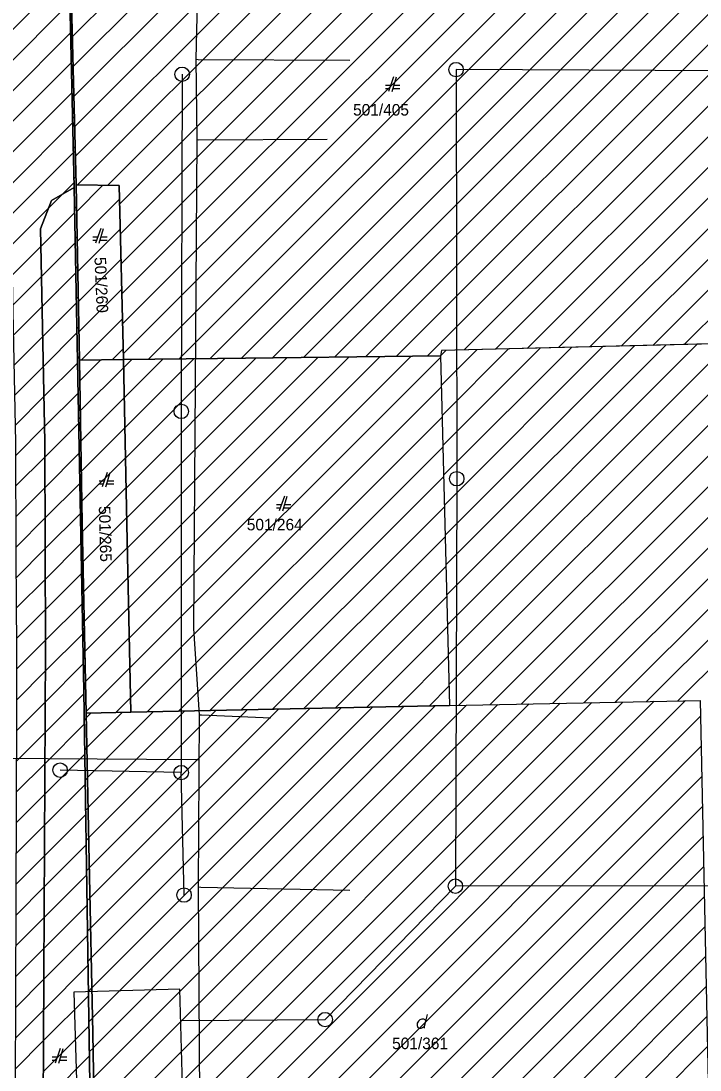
# Model space of a CAD drawing. Extents: x -264309 to -263505, y -1242443 to -1241763.
# Drawn here: x -263948.8 to -263854.8, y -1242246.2 to -1242101 of the extents above; entities that cross this region are included whole.
import ezdxf

# ---------------------------------------------------------------- set-up
doc = ezdxf.new("R2010")
doc.units = 0
for name, color, linetype in [('KFA_DAZDOVA_KANALIZACIA_retencna_nadrz', 7, 'Continuous'), ('KFA_DAZDOVA_KANALIZACIA_vetva_G', 7, 'Continuous'), ('KFA_DAZDOVA_KANALIZACIA_vetva_I', 7, 'Continuous'), ('KFA_SO_50-1-II_VODOVODNE_PRIPOJKY', 7, 'Continuous'), ('KFA_SO_50-2_POZIARNY_VODOVOD_TRASA', 7, 'Continuous'), ('KN_2019_08_16_KLADPAR', 7, 'Continuous'), ('SRAFY_PARCELY', 7, 'Continuous')]:
    doc.layers.add(name, color=color, linetype=linetype)

msp = doc.modelspace()

# ---------------------------------------------------------------- linework, layer by layer
at = {"layer": 'KFA_DAZDOVA_KANALIZACIA_retencna_nadrz'}
msp.add_lwpolyline([(-263941.49, -1242235.46), (-263940.97, -1242253.75), (-263926.32, -1242253.31), (-263926.85, -1242235.04)], close=True, dxfattribs=at)
at = {"layer": 'KFA_DAZDOVA_KANALIZACIA_vetva_G'}
for points in [[(-263926.52, -1242108.42), (-263926.64, -1242155.08), (-263926.65, -1242205.07)], [(-263926.26, -1242222.02), (-263926.65, -1242205.07), (-263943.42, -1242204.73)]]:
    msp.add_lwpolyline(points, dxfattribs=at)
for centre in [(-263926.52, -1242108.42), (-263926.64, -1242155.08), (-263943.42, -1242204.73), (-263926.65, -1242205.07), (-263926.26, -1242222.02)]:
    msp.add_circle(centre, 1, dxfattribs=at)
at = {"layer": 'KFA_DAZDOVA_KANALIZACIA_vetva_I'}
msp.add_line((-263926.72, -1242239.4), (-263906.73, -1242239.26), dxfattribs=at)
for points in [[(-263814.91, -1242107.86), (-263815.2, -1242164.44), (-263815.19, -1242220.79), (-263852.15, -1242220.74), (-263888.7, -1242220.79), (-263906.73, -1242239.26)], [(-263814.91, -1242107.86), (-263851.89, -1242107.95), (-263888.61, -1242107.77), (-263888.52, -1242164.4), (-263888.7, -1242220.79)]]:
    msp.add_lwpolyline(points, dxfattribs=at)
for centre in [(-263888.61, -1242107.77), (-263888.52, -1242164.4), (-263888.7, -1242220.79), (-263906.73, -1242239.26)]:
    msp.add_circle(centre, 1, dxfattribs=at)
at = {"layer": 'KFA_SO_50-1-II_VODOVODNE_PRIPOJKY'}
for points in [[(-263924.64, -1242106.32), (-263924.32, -1242106.37), (-263903.32, -1242106.48)], [(-263924.48, -1242117.43), (-263924.21, -1242117.48), (-263906.47, -1242117.4)], [(-263924.15, -1242197.09), (-263923.86, -1242197.09), (-263914.23, -1242197.47)], [(-263924.19, -1242203.3), (-263924.63, -1242203.3), (-263958.87, -1242203.05)], [(-263924.3, -1242220.9), (-263923.93, -1242220.91), (-263903.3, -1242221.32)]]:
    msp.add_lwpolyline(points, dxfattribs=at)
at = {"layer": 'KFA_SO_50-2_POZIARNY_VODOVOD_TRASA'}
msp.add_lwpolyline([(-263924.93, -1242185.13), (-263924.15, -1242197.09), (-263924.3, -1242220.9), (-263924.1, -1242250.12), (-263913.99, -1242249.8), (-263886.91, -1242249.88), (-263867.71, -1242249.83), (-263837.26, -1242249.84), (-263828.16, -1242249.9), (-263787.99, -1242250.03), (-263788.2, -1242220.84), (-263788.2, -1242200.51), (-263788.09, -1242179.92), (-263788.06, -1242148.96), (-263787.92, -1242127.95), (-263787.95, -1242110.97), (-263788.13, -1242082.54), (-263828.43, -1242082.72), (-263836.78, -1242082.56), (-263867.31, -1242082.61), (-263886.71, -1242082.47), (-263924.08, -1242082.61), (-263924.64, -1242106.32), (-263924.48, -1242117.43)], close=True, dxfattribs=at)
at = {"layer": 'KN_2019_08_16_KLADPAR'}
for p, q in [((-263897.27, -1242108.78), (-263897.97, -1242110.78)), ((-263897.47, -1242110.78), (-263896.87, -1242108.78)), ((-263897.69, -1242109.98), (-263898.37, -1242109.98)), ((-263896.37, -1242109.98), (-263897.23, -1242109.98)), ((-263898.37, -1242110.38), (-263897.83, -1242110.38)), ((-263897.35, -1242110.38), (-263896.37, -1242110.38)), ((-263937.79, -1242129.77), (-263938.49, -1242131.77)), ((-263937.99, -1242131.77), (-263937.39, -1242129.77)), ((-263938.21, -1242130.97), (-263938.89, -1242130.97)), ((-263938.89, -1242131.37), (-263938.35, -1242131.37)), ((-263937.87, -1242131.37), (-263936.89, -1242131.37)), ((-263936.89, -1242130.97), (-263937.75, -1242130.97)), ((-263936.89, -1242163.52), (-263937.59, -1242165.52)), ((-263937.09, -1242165.52), (-263936.49, -1242163.52)), ((-263937.31, -1242164.72), (-263937.99, -1242164.72)), ((-263937.99, -1242165.12), (-263937.45, -1242165.12)), ((-263936.97, -1242165.12), (-263935.99, -1242165.12)), ((-263935.99, -1242164.72), (-263936.85, -1242164.72)), ((-263912.37, -1242166.83), (-263913.07, -1242168.83)), ((-263912.57, -1242168.83), (-263911.97, -1242166.83)), ((-263912.79, -1242168.03), (-263913.47, -1242168.03)), ((-263911.47, -1242168.03), (-263912.33, -1242168.03)), ((-263913.47, -1242168.43), (-263912.93, -1242168.43)), ((-263912.45, -1242168.43), (-263911.47, -1242168.43)), ((-263892.81, -1242239.46), (-263892.54, -1242238.56)), ((-263943.39, -1242243.27), (-263944.09, -1242245.27)), ((-263943.59, -1242245.27), (-263942.99, -1242243.27)), ((-263943.81, -1242244.47), (-263944.49, -1242244.47)), ((-263944.49, -1242244.87), (-263943.95, -1242244.87)), ((-263943.47, -1242244.87), (-263942.49, -1242244.87)), ((-263942.49, -1242244.47), (-263943.35, -1242244.47))]:
    msp.add_line(p, q, dxfattribs=at)
for points in [[(-263945.92, -1242287.35), (-263949.74, -1242287.63), (-263949.41, -1242196.68), (-263949.38, -1242187.85), (-263949.49, -1242175.05), (-263949.55, -1242159.39), (-263950.14, -1242129.96), (-263950.48, -1242111.43), (-263955.8, -1242087.79), (-263956.24, -1242069.24), (-263949.96, -1242070.83), (-263947.13, -1242072.33), (-263942.68, -1242071.91), (-263941.47, -1242124.08), (-263944.59, -1242125.87), (-263946.11, -1242129.79), (-263945.51, -1242159.3), (-263945.41, -1242187.87)], [(-263942.54, -1242071.9), (-263846.54, -1242085.45), (-263846.27, -1242096.79), (-263846.29, -1242099.09), (-263845.63, -1242123.54), (-263845.17, -1242145.54), (-263890.62, -1242146.65), (-263890.76, -1242147.37), (-263921.62, -1242147.75), (-263934.65, -1242147.91), (-263935.23, -1242123.81), (-263941.18, -1242123.7)], [(-263945.92, -1242287.35), (-263945.41, -1242187.87), (-263945.51, -1242159.3), (-263946.11, -1242129.79), (-263944.59, -1242125.87), (-263941.47, -1242124.08), (-263940.13, -1242193.8), (-263938.35, -1242311.44), (-263946.05, -1242311.56)], [(-263940.74, -1242147.99), (-263941.18, -1242123.7), (-263935.23, -1242123.81), (-263934.65, -1242147.91)], [(-263939.79, -1242196.85), (-263940.34, -1242170.51), (-263940.74, -1242147.99), (-263934.65, -1242147.91), (-263934.15, -1242172.94), (-263933.6, -1242196.72)], [(-263934.65, -1242147.91), (-263921.62, -1242147.75), (-263890.76, -1242147.37), (-263889.52, -1242195.8), (-263933.6, -1242196.72), (-263934.15, -1242172.94)], [(-263939.79, -1242196.85), (-263933.6, -1242196.72), (-263889.52, -1242195.8), (-263854.81, -1242195.07), (-263852.5, -1242305.04), (-263931.11, -1242306.7), (-263937.48, -1242306.83), (-263938.02, -1242292.26), (-263938.87, -1242241.14), (-263939.37, -1242217.33)]]:
    msp.add_lwpolyline(points, close=True, dxfattribs=at)
for points in [[(-263942.54, -1242071.9), (-263941.18, -1242123.7), (-263940.74, -1242147.99), (-263940.34, -1242170.51), (-263939.79, -1242196.85), (-263939.37, -1242217.33), (-263938.87, -1242241.14), (-263938.02, -1242292.26), (-263937.48, -1242306.83), (-263937.4, -1242310.7), (-263938.35, -1242311.44), (-263940.13, -1242193.8), (-263941.47, -1242124.08), (-263942.68, -1242071.91)], [(-263892.99, -1242240.45), (-263892.99, -1242240.18), (-263892.81, -1242239.46), (-263892.9, -1242239.28), (-263893.08, -1242239.19), (-263893.35, -1242239.19), (-263893.62, -1242239.28), (-263893.8, -1242239.46), (-263893.98, -1242239.73), (-263893.98, -1242240.09), (-263893.89, -1242240.36), (-263893.71, -1242240.45), (-263893.44, -1242240.45), (-263893.26, -1242240.36), (-263892.99, -1242240.18)]]:
    msp.add_lwpolyline(points, dxfattribs=at)
at = {"layer": 'SRAFY_PARCELY'}
for p, q in [((-263941.72, -1242103.22), (-263914.37, -1242075.88)), ((-263941.61, -1242107.36), (-263910.65, -1242076.4)), ((-263941.5, -1242111.49), (-263906.93, -1242076.93)), ((-263941.39, -1242115.63), (-263903.22, -1242077.45)), ((-263941.28, -1242119.76), (-263899.5, -1242077.98)), ((-263940.98, -1242123.7), (-263895.78, -1242078.5)), ((-263936.82, -1242123.78), (-263892.06, -1242079.02)), ((-263935.17, -1242126.37), (-263888.34, -1242079.55)), ((-263935.07, -1242130.52), (-263884.63, -1242080.07)), ((-263934.97, -1242134.66), (-263880.91, -1242080.6)), ((-263934.87, -1242138.8), (-263877.19, -1242081.12)), ((-263934.77, -1242142.95), (-263873.47, -1242081.65)), ((-263934.67, -1242147.09), (-263869.75, -1242082.17)), ((-263931.21, -1242147.87), (-263866.04, -1242082.7)), ((-263926.91, -1242147.81), (-263862.32, -1242083.22)), ((-263922.62, -1242147.76), (-263858.6, -1242083.75)), ((-263918.32, -1242147.71), (-263854.88, -1242084.27)), ((-263914.02, -1242147.66), (-263851.17, -1242084.8)), ((-263909.73, -1242147.6), (-263847.45, -1242085.32)), ((-263905.43, -1242147.55), (-263846.47, -1242088.58)), ((-263901.14, -1242147.5), (-263846.37, -1242092.73)), ((-263952.08, -1242104.31), (-263942.16, -1242094.39)), ((-263896.84, -1242147.44), (-263846.27, -1242096.87)), ((-263951.3, -1242107.78), (-263942.06, -1242098.54)), ((-263892.55, -1242147.39), (-263846.24, -1242101.08)), ((-263950.52, -1242111.24), (-263941.97, -1242102.68)), ((-263941.98, -1242102.1), (-263941.75, -1242101.87)), ((-263887.49, -1242146.57), (-263846.12, -1242105.21)), ((-263950.41, -1242115.37), (-263941.87, -1242106.83)), ((-263941.88, -1242106.24), (-263941.64, -1242106)), ((-263941.79, -1242110.39), (-263941.54, -1242110.14)), ((-263883.14, -1242146.47), (-263846.01, -1242109.34)), ((-263950.33, -1242119.54), (-263941.77, -1242110.98)), ((-263941.69, -1242114.54), (-263941.43, -1242114.27)), ((-263878.79, -1242146.36), (-263845.9, -1242113.47)), ((-263950.25, -1242123.7), (-263941.68, -1242115.12)), ((-263941.6, -1242118.68), (-263941.32, -1242118.41)), ((-263874.44, -1242146.25), (-263845.79, -1242117.61)), ((-263950.18, -1242127.87), (-263941.58, -1242119.27)), ((-263870.09, -1242146.15), (-263845.68, -1242121.74)), ((-263941.5, -1242122.83), (-263941.21, -1242122.54)), ((-263943.06, -1242124.99), (-263941.49, -1242123.42)), ((-263941.11, -1242127.4), (-263937.48, -1242123.77)), ((-263945, -1242126.93), (-263943.07, -1242125)), ((-263941.04, -1242131.56), (-263935.18, -1242125.71)), ((-263865.74, -1242146.04), (-263845.58, -1242125.88)), ((-263950.1, -1242132.03), (-263945, -1242126.93)), ((-263946.06, -1242132.23), (-263941.4, -1242127.57)), ((-263941.41, -1242126.99), (-263941.13, -1242126.7)), ((-263940.96, -1242135.73), (-263935.08, -1242129.85)), ((-263861.39, -1242145.94), (-263845.49, -1242130.04)), ((-263945.98, -1242136.39), (-263941.32, -1242131.74)), ((-263941.33, -1242131.15), (-263941.05, -1242130.87)), ((-263950.02, -1242136.19), (-263946.06, -1242132.23)), ((-263940.89, -1242139.9), (-263934.98, -1242134)), ((-263857.04, -1242145.83), (-263845.41, -1242134.19)), ((-263949.93, -1242140.35), (-263945.98, -1242136.39)), ((-263945.89, -1242140.55), (-263941.24, -1242135.9)), ((-263941.25, -1242135.31), (-263940.97, -1242135.03)), ((-263941.17, -1242139.48), (-263940.9, -1242139.2)), ((-263940.81, -1242144.07), (-263934.89, -1242138.14)), ((-263949.85, -1242144.51), (-263945.89, -1242140.55)), ((-263945.81, -1242144.71), (-263941.16, -1242140.06)), ((-263941.09, -1242143.64), (-263940.82, -1242143.37)), ((-263940.49, -1242147.99), (-263934.79, -1242142.28)), ((-263949.76, -1242148.67), (-263945.81, -1242144.71)), ((-263945.72, -1242148.86), (-263941.08, -1242144.22)), ((-263936.19, -1242147.93), (-263934.69, -1242146.42)), ((-263890.65, -1242151.51), (-263885.68, -1242146.53)), ((-263845.17, -1242145.54), (-263890.62, -1242146.65)), ((-263890.55, -1242155.64), (-263881.33, -1242146.42)), ((-263890.44, -1242159.78), (-263876.98, -1242146.32)), ((-263890.34, -1242163.92), (-263872.63, -1242146.21)), ((-263890.23, -1242168.05), (-263868.28, -1242146.1)), ((-263890.12, -1242172.19), (-263863.93, -1242146)), ((-263890.02, -1242176.33), (-263859.58, -1242145.89)), ((-263889.91, -1242180.46), (-263855.24, -1242145.79)), ((-263889.81, -1242184.6), (-263850.89, -1242145.68)), ((-263889.7, -1242188.74), (-263846.54, -1242145.57)), ((-263889.59, -1242192.87), (-263842.56, -1242145.84)), ((-263888.25, -1242195.77), (-263838.73, -1242146.25)), ((-263883.92, -1242195.68), (-263834.4, -1242146.16)), ((-263879.59, -1242195.59), (-263830.07, -1242146.08)), ((-263875.25, -1242195.5), (-263825.74, -1242145.99)), ((-263870.92, -1242195.41), (-263821.42, -1242145.91)), ((-263866.58, -1242195.32), (-263817.09, -1242145.82)), ((-263862.25, -1242195.23), (-263812.76, -1242145.74)), ((-263857.92, -1242195.14), (-263808.44, -1242145.66)), ((-263941.01, -1242147.8), (-263940.75, -1242147.53)), ((-263940.69, -1242150.85), (-263937.79, -1242147.95)), ((-263934.63, -1242149.05), (-263933.47, -1242147.9)), ((-263934.54, -1242153.21), (-263929.18, -1242147.84)), ((-263934.46, -1242157.37), (-263924.88, -1242147.79)), ((-263934.38, -1242161.53), (-263920.59, -1242147.74)), ((-263934.29, -1242165.69), (-263916.29, -1242147.68)), ((-263934.21, -1242169.85), (-263912, -1242147.63)), ((-263934.13, -1242174), (-263907.7, -1242147.58)), ((-263934.03, -1242178.15), (-263903.41, -1242147.53)), ((-263933.93, -1242182.3), (-263899.11, -1242147.47)), ((-263933.84, -1242186.44), (-263894.81, -1242147.42)), ((-263933.74, -1242190.59), (-263890.75, -1242147.6)), ((-263890.76, -1242147.37), (-263890.03, -1242146.64)), ((-263890.62, -1242146.65), (-263890.76, -1242147.37)), ((-263890.76, -1242147.37), (-263889.52, -1242195.8)), ((-263949.68, -1242152.83), (-263945.72, -1242148.87)), ((-263945.64, -1242153.02), (-263941, -1242148.39)), ((-263940.62, -1242155.02), (-263934.63, -1242149.03)), ((-263940.93, -1242151.96), (-263940.67, -1242151.7)), ((-263933.65, -1242194.74), (-263890.65, -1242151.74)), ((-263949.6, -1242156.99), (-263945.64, -1242153.03)), ((-263945.55, -1242157.18), (-263940.92, -1242152.55)), ((-263940.54, -1242159.18), (-263934.54, -1242153.19)), ((-263945.5, -1242161.37), (-263940.84, -1242156.71)), ((-263940.85, -1242156.13), (-263940.6, -1242155.87)), ((-263931.34, -1242196.67), (-263890.54, -1242155.88)), ((-263949.54, -1242161.17), (-263945.55, -1242157.18)), ((-263940.47, -1242163.35), (-263934.46, -1242157.35)), ((-263945.49, -1242165.6), (-263940.76, -1242160.87)), ((-263940.77, -1242160.29), (-263940.53, -1242160.04)), ((-263927.01, -1242196.58), (-263890.44, -1242160.01)), ((-263949.53, -1242165.4), (-263945.5, -1242161.38)), ((-263940.39, -1242167.52), (-263934.38, -1242161.51)), ((-263945.47, -1242169.83), (-263940.68, -1242165.04)), ((-263940.69, -1242164.45), (-263940.45, -1242164.21)), ((-263922.67, -1242196.49), (-263890.33, -1242164.15)), ((-263949.51, -1242169.63), (-263945.49, -1242165.6)), ((-263940.32, -1242171.69), (-263934.3, -1242165.67)), ((-263940.61, -1242168.61), (-263940.38, -1242168.38)), ((-263918.34, -1242196.4), (-263890.22, -1242168.29)), ((-263949.49, -1242173.85), (-263945.47, -1242169.83)), ((-263945.46, -1242174.06), (-263940.6, -1242169.2)), ((-263940.23, -1242175.84), (-263934.21, -1242169.83)), ((-263940.53, -1242172.78), (-263940.3, -1242172.54)), ((-263914.01, -1242196.31), (-263890.12, -1242172.42)), ((-263949.46, -1242178.06), (-263945.46, -1242174.06)), ((-263945.44, -1242178.28), (-263940.52, -1242173.36)), ((-263940.14, -1242180), (-263934.13, -1242173.98)), ((-263940.45, -1242176.94), (-263940.21, -1242176.7)), ((-263909.67, -1242196.22), (-263890.01, -1242176.56)), ((-263949.43, -1242182.27), (-263945.44, -1242178.29)), ((-263945.43, -1242182.51), (-263940.44, -1242177.53)), ((-263940.06, -1242184.15), (-263934.03, -1242178.13)), ((-263940.37, -1242181.1), (-263940.12, -1242180.85)), ((-263905.34, -1242196.13), (-263889.91, -1242180.7)), ((-263949.39, -1242186.48), (-263945.43, -1242182.51)), ((-263945.41, -1242186.74), (-263940.36, -1242181.69)), ((-263939.97, -1242188.31), (-263933.93, -1242182.28)), ((-263940.29, -1242185.26), (-263940.04, -1242185.01)), ((-263901.01, -1242196.04), (-263889.8, -1242184.83)), ((-263949.39, -1242190.72), (-263945.41, -1242186.74)), ((-263945.43, -1242190.99), (-263940.28, -1242185.85)), ((-263939.88, -1242192.47), (-263933.84, -1242186.42)), ((-263945.45, -1242195.26), (-263940.2, -1242190.01)), ((-263940.21, -1242189.43), (-263939.95, -1242189.16)), ((-263896.67, -1242195.95), (-263889.69, -1242188.97)), ((-263949.4, -1242194.98), (-263945.43, -1242191)), ((-263939.79, -1242196.62), (-263933.74, -1242190.57)), ((-263945.47, -1242199.52), (-263940.12, -1242194.18)), ((-263940.13, -1242193.59), (-263939.86, -1242193.32)), ((-263892.34, -1242195.86), (-263889.59, -1242193.11)), ((-263949.42, -1242199.23), (-263945.45, -1242195.26)), ((-263938.91, -1242239), (-263895.85, -1242195.93)), ((-263938.84, -1242243.17), (-263891.51, -1242195.84)), ((-263938.77, -1242247.34), (-263887.18, -1242195.75)), ((-263938.7, -1242251.51), (-263882.84, -1242195.66)), ((-263938.63, -1242255.69), (-263878.51, -1242195.57)), ((-263938.56, -1242259.86), (-263874.18, -1242195.48)), ((-263938.49, -1242264.03), (-263869.84, -1242195.39)), ((-263938.42, -1242268.21), (-263865.51, -1242195.3)), ((-263938.35, -1242272.38), (-263861.18, -1242195.2)), ((-263938.28, -1242276.55), (-263856.84, -1242195.11)), ((-263935.69, -1242196.76), (-263933.65, -1242194.72)), ((-263889.52, -1242195.8), (-263854.81, -1242195.07)), ((-263939.78, -1242197.44), (-263939.18, -1242196.84)), ((-263939.69, -1242201.6), (-263934.84, -1242196.75)), ((-263939.61, -1242205.75), (-263930.51, -1242196.66)), ((-263939.52, -1242209.91), (-263926.18, -1242196.57)), ((-263939.44, -1242214.07), (-263921.84, -1242196.47)), ((-263939.35, -1242218.22), (-263917.51, -1242196.38)), ((-263939.26, -1242222.38), (-263913.18, -1242196.29)), ((-263939.18, -1242226.54), (-263908.84, -1242196.2)), ((-263939.09, -1242230.69), (-263904.51, -1242196.11)), ((-263939, -1242234.85), (-263900.18, -1242196.02)), ((-263938.21, -1242280.72), (-263854.76, -1242197.28)), ((-263945.49, -1242203.79), (-263940.06, -1242198.36)), ((-263940.07, -1242197.77), (-263939.78, -1242197.48)), ((-263949.43, -1242203.49), (-263945.47, -1242199.53)), ((-263940.01, -1242201.95), (-263939.69, -1242201.63)), ((-263938.14, -1242284.9), (-263854.68, -1242201.43)), ((-263945.51, -1242208.05), (-263940, -1242202.54)), ((-263949.45, -1242207.75), (-263945.49, -1242203.79)), ((-263939.94, -1242206.13), (-263939.61, -1242205.79)), ((-263938.07, -1242289.07), (-263854.59, -1242205.59)), ((-263945.54, -1242212.32), (-263939.93, -1242206.72)), ((-263949.47, -1242212.01), (-263945.51, -1242208.06)), ((-263939.88, -1242210.31), (-263939.52, -1242209.95)), ((-263937.98, -1242293.23), (-263854.5, -1242209.74)), ((-263945.56, -1242216.58), (-263939.87, -1242210.89)), ((-263949.48, -1242216.27), (-263945.54, -1242212.32)), ((-263939.82, -1242214.49), (-263939.44, -1242214.1)), ((-263937.83, -1242297.32), (-263854.41, -1242213.9)), ((-263945.58, -1242220.85), (-263939.81, -1242215.07)), ((-263949.5, -1242220.52), (-263945.56, -1242216.58)), ((-263939.75, -1242218.67), (-263939.35, -1242218.26)), ((-263937.68, -1242301.41), (-263854.33, -1242218.05)), ((-263945.6, -1242225.11), (-263939.74, -1242219.25)), ((-263949.51, -1242224.78), (-263945.58, -1242220.85)), ((-263945.62, -1242229.37), (-263939.68, -1242223.43)), ((-263939.69, -1242222.84), (-263939.26, -1242222.42)), ((-263937.53, -1242305.5), (-263854.24, -1242222.21)), ((-263949.53, -1242229.04), (-263945.6, -1242225.11)), ((-263934.56, -1242306.77), (-263854.15, -1242226.36)), ((-263945.64, -1242233.64), (-263939.62, -1242227.61)), ((-263939.63, -1242227.02), (-263939.18, -1242226.57)), ((-263949.54, -1242233.3), (-263945.62, -1242229.38)), ((-263939.56, -1242231.2), (-263939.09, -1242230.73)), ((-263930.23, -1242306.68), (-263854.07, -1242230.52)), ((-263945.67, -1242237.9), (-263939.56, -1242231.79)), ((-263949.56, -1242237.56), (-263945.64, -1242233.64)), ((-263939.5, -1242235.38), (-263939, -1242234.88)), ((-263925.89, -1242306.59), (-263853.98, -1242234.67)), ((-263945.69, -1242242.17), (-263939.49, -1242235.97)), ((-263949.57, -1242241.81), (-263945.67, -1242237.91)), ((-263939.44, -1242239.56), (-263938.91, -1242239.04)), ((-263921.56, -1242306.5), (-263853.89, -1242238.83)), ((-263945.71, -1242246.43), (-263939.43, -1242240.15)), ((-263949.59, -1242246.07), (-263945.69, -1242242.17)), ((-263939.37, -1242243.74), (-263938.84, -1242243.2)), ((-263917.22, -1242306.41), (-263853.8, -1242242.99)), ((-263945.73, -1242250.7), (-263939.37, -1242244.33))]:
    msp.add_line(p, q, dxfattribs=at)

# ---------------------------------------------------------------- texts
at = {"layer": 'KN_2019_08_16_KLADPAR'}
for s, p in [('501/405', (-263902.86, -1242114.13)), ('501/264', (-263917.57, -1242171.54)), ('501/361', (-263897.46, -1242243.35))]:
    msp.add_text(s, height=1.6, dxfattribs=at).set_placement(p)
for s, rotation, p in [('501/260', 272.3841, (-263938.66, -1242133.74)), ('501/265', 271.5247, (-263938.06, -1242168.19))]:
    msp.add_text(s, height=1.6, rotation=rotation, dxfattribs=at).set_placement(p)

doc.saveas('drawing.dxf')
